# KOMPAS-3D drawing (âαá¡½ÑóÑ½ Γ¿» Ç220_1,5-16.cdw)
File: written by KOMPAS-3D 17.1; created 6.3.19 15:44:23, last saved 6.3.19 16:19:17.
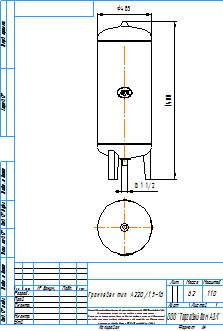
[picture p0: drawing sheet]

Sheet 1: A4, portrait

Title block, sheet 1: name: Гранлевел тип А220/1,5-16; material: Сталь 10  ГОСТ 1050-88; mass: 62; sheets: 1; sheet format: A4; stored path: C:\Users\kka\KOMPAS_Work\!Trash\ГРАНЛЕВЕЛ тип А Расширительный бак\KOMPAS 2D\Гранлевел тип А220_1,5-16.cdw

Views: Вид 1, Проекционный вид 2
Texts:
  kka
  adl
  Рама для чертежей
  Лит-Масса-Масштаб
  Материал-Предприятие
  Масштаб
  Изм.
  Лист
  № докум.
  Подп.
  Дата
  Лит.
  Разраб.
  Пров.
  Т.контр.
  Листов
  Внимание! Данный продукт является объектом авторского права ООО «Торговый Дом АДЛ».
  Запрещается изменение, копирование, распространение
  (в том числе путем копирования на другие сайты и ресурсы в Интернете)
  или любое иное использование информации и объектов без предварительного
  согласия правообладателя (ООО «Торговый Дом АДЛ»).
  Н.контр.
  Утв.
  ООО "Торговый дом АДЛ"
  Изменение
  Номер документа
  Подпись
  Обозначение документа
  Наименование изделия
  Масса изделия по ГОСТ 2.109-73
  Порядковый номер листа
  Общее количество листов в документе
  Характер работы, выполненной лицом, подписавшим документ
  Наименование или индекс предприятия, выпускающего документ
  Инв. № подл.
  Подп. и дата
  Взам. инв. №
  Инв. № дубл.
  Инвентарный номер подлинника по ГОСТ 2.501-68
  Подпись принявшего подлинник в отдел технической документации
  Инвентарный номер подлинника, взамен которого выпущен данный подлинник
  Инвентарный номер дубликата по ГОСТ 2.502-68
  Подпись принявшего дубликат в отдел технической документации
  Справ. №
  Перв. примен.
  Обозначение документа, взамен или на основании которого выпущен данный документ
  Обозначение документа, в котором впервые записан данный документ
  Подпись лица, копировавшего чертеж
  Обозначение формата листа
  !Рама для чертежа
Dimensions and other numbers on the sheet: 1400; 485; 1 1/2; 1:10; 1; 62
